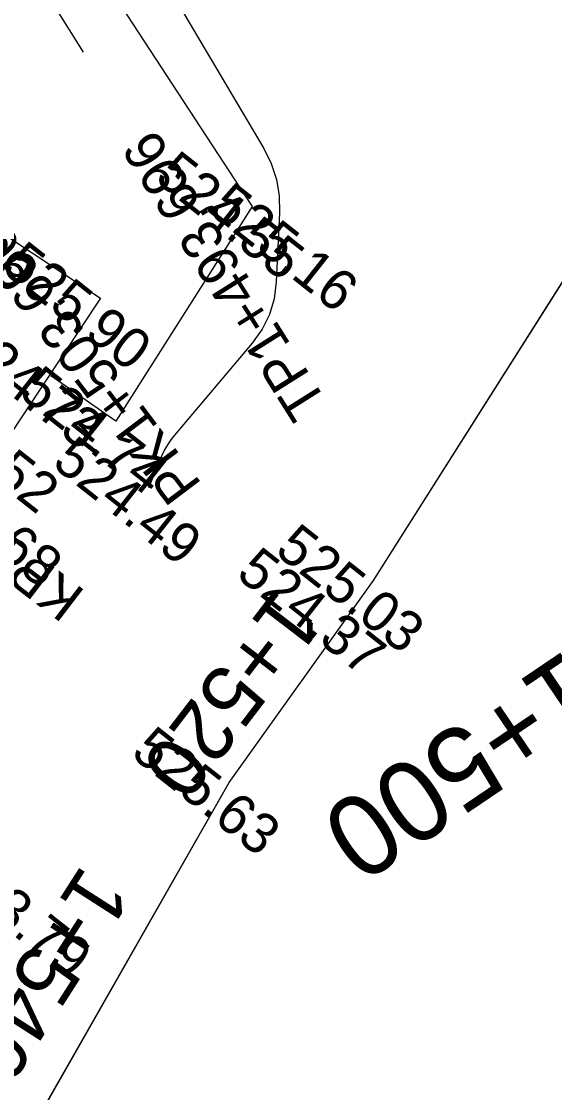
# Model space of a CAD drawing. Extents: x -636600 to -628587, y -1090963 to -1085869.
# Drawn here: x -629757.1 to -629730.7, y -1089822.7 to -1089769.7 of the extents above; entities that cross this region are included whole.
import ezdxf

# ---------------------------------------------------------------- set-up
doc = ezdxf.new("R2010")
doc.units = 0
for name, color, linetype in [('20', 7, 'Continuous'), ('21', 7, 'Continuous'), ('23', 7, 'Continuous'), ('Ex_Minor Contours', 7, 'Continuous'), ('HEKTOMETRY100', 7, 'Continuous'), ('HEKTOMETRY20', 7, 'Continuous'), ('HL_BODY', 7, 'Continuous'), ('koty_vše', 7, 'Continuous'), ('PARCELY_NÁVRH_SILNICE_ŽELEZNICE', 7, 'Continuous')]:
    doc.layers.add(name, color=color, linetype=linetype)

msp = doc.modelspace()

# ---------------------------------------------------------------- linework, layer by layer
at = {"layer": '20'}
for p, q in [((-629759.004, -1089779.517), (-629753.159, -1089783.377)), ((-629753.159, -1089783.377), (-629757.802, -1089790.375))]:
    msp.add_line(p, q, dxfattribs=at)
at = {"layer": '21'}
for p, q in [((-629739.641, -1089797.354), (-629724.72, -1089773.793)), ((-629746.798, -1089807.362), (-629739.641, -1089797.354)), ((-629763.53, -1089836.705), (-629746.798, -1089807.362))]:
    msp.add_line(p, q, dxfattribs=at)
at = {"layer": '23'}
for p, q in [((-629755.349, -1089764.02), (-629745.662, -1089778.847)), ((-629745.662, -1089778.847), (-629752.404, -1089789.475)), ((-629752.404, -1089789.475), (-629755.632, -1089787.222))]:
    msp.add_line(p, q, dxfattribs=at)
at = {"layer": 'Ex_Minor Contours'}
msp.add_lwpolyline([(-629751.947, -1089764.372), (-629745.083, -1089775.97), (-629744.707, -1089776.723), (-629744.449, -1089777.505), (-629744.312, -1089778.316), (-629744.293, -1089779.158), (-629744.459, -1089782.582), (-629744.565, -1089783.413), (-629744.799, -1089784.194), (-629745.16, -1089784.924), (-629745.65, -1089785.603), (-629749.506, -1089790.157), (-629749.689, -1089790.392), (-629749.853, -1089790.638), (-629749.997, -1089790.897), (-629750.121, -1089791.167), (-629750.772, -1089792.746), (-629750.784, -1089792.771)], dxfattribs=at)
at = {"layer": 'HL_BODY'}
msp.add_lwpolyline([(-629759.344, -1089762.734), (-629754.017, -1089771.197)], dxfattribs=at)
at = {"layer": 'PARCELY_NÁVRH_SILNICE_ŽELEZNICE'}
msp.add_lwpolyline([(-629636.498, -1089682.368), (-629669.229, -1089703.189), (-629693.039, -1089722.565), (-629715.944, -1089740.02), (-629755.349, -1089764.02), (-629773.774, -1089778.258), (-629775.661, -1089789.328), (-629789.014, -1089815.993), (-629763.271, -1089834.375), (-629762.496, -1089834.892), (-629746.798, -1089807.362), (-629739.641, -1089797.354), (-629724.72, -1089773.793), (-629704.711, -1089750.564), (-629683.036, -1089730.713), (-629659.95, -1089713.109)], dxfattribs=at)

# ---------------------------------------------------------------- texts
at = {"layer": 'HEKTOMETRY100'}
msp.add_text('1+500', height=4, rotation=214.0851, dxfattribs=at).set_placement((-629730.059, -1089800.706))
at = {"layer": 'HEKTOMETRY20'}
for s, rotation, p in [('1+520', 232.5314, (-629744.408, -1089797.634)), ('1+540', 237.3306, (-629754.06, -1089811.339))]:
    msp.add_text(s, height=3, rotation=rotation, dxfattribs=at).set_placement(p)
at = {"layer": 'HL_BODY'}
for s, rotation, p in [('TP1+493,696', 122.1878, (-629741.888, -1089788.589)), ('PK1+503,696', 126.9624, (-629748.106, -1089792.605)), ('KP1+520,026', 142.556, (-629753.85, -1089797.918))]:
    msp.add_text(s, height=2, rotation=rotation, dxfattribs=at).set_placement(p)
at = {"layer": 'koty_vše'}
for s, p in [('524.55', (-629750.547, -1089777.54)), ('525.99', (-629763.902, -1089778.2)), ('525.16', (-629747.884, -1089779.107)), ('525.90', (-629758.119, -1089782.011)), ('524.73', (-629760.517, -1089785.914)), ('524.74', (-629757.29, -1089788.168)), ('524.52', (-629762.687, -1089789.068)), ('524.49', (-629755.631, -1089791.655)), ('524.68', (-629762.521, -1089792.74)), ('525.03', (-629744.595, -1089795.993)), ('524.37', (-629746.519, -1089797.151)), ('525.63', (-629751.727, -1089806.021)), ('523.79', (-629761.066, -1089812.104))]:
    msp.add_text(s, height=2, rotation=321.7265, dxfattribs=at).set_placement(p)

doc.saveas('drawing.dxf')
